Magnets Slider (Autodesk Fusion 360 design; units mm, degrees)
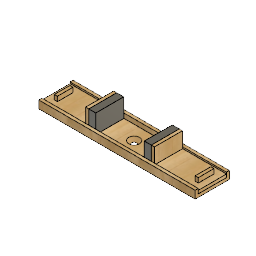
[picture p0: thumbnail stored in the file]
parameter "Mag_L" = 180
parameter "Mag_W" = 120
parameter "Mag_T" = 45
sketch "Sketch1"
  dimension "d1" = 220 (= "Mag_L + 40 mm")
  dimension "d2" = 1000
extrude "Extrude1" new body sketch "Sketch1" blind 50
sketch "Sketch2" plane through (0, 0, 50) normal (0, 0, 1) x axis (-1, 0, 0)
  dimension "d6" = 180 (= "Mag_L")
extrude "Extrude2" cut sketch "Sketch2" against normal blind 30
sketch "Sketch4" plane through (0, 0, 20) normal (0, 0, 1) x axis (-1, 0, 0)
  dimension "d10" = 70
extrude "Extrude3" cut sketch "Sketch4" against normal blind 20 taper -45
component_from_bodies "Body->Comp"
sketch "Sketch1" plane through (0, 0, 20) normal (0, 0, 1) x axis (-1, 0, 0)
  dimension "d13" = 280
  dimension "d14" = 180 (= "Mag_L")
  dimension "d22" = 0
  dimension "d23" = 0
  dimension "d24" = 0
  dimension "d25" = 0
extrude "Extrude1" new body sketch "Sketch1" along normal blind 20
sketch "Sketch2" plane through (125, 0, 0) normal (-1, 0, 0) x axis (0, -1, 0)
  dimension "d18" = 180 (= "Mag_L")
  dimension "d19" = 120 (= "Mag_W")
extrude "Extrude2" add sketch "Sketch2" along normal blind 20
position "Position1"
joint "Assemble1" sketch "Sketch2" alignAngle 0 alignOffsetX 0 alignOffsetY 0 alignOffsetZ 0
copy_paste_bodies "CopyPasteBodies1"
position "Position2" TranslateAlongX 350
move "Move1"
joint "Assemble2" alignAngle 180 alignOffsetX 0 alignOffsetY 0 alignOffsetZ 0
sketch "Sketch1" plane through (-238.0829, 32.402, -22.7743) normal (1, 0, 0) x axis (0, 1, 0)
  dimension "d55" = 120 (= "Mag_W")
  dimension "d56" = 180 (= "Mag_L")
extrude "Extrude1" new body sketch "Sketch1" along normal blind 45 (= "Mag_T")
sketch "Sketch2" plane through (161.9171, 0, 0) normal (-1, 0, 0) x axis (0, -1, 0)
  dimension "d61" = 120 (= "Mag_W")
  dimension "d62" = 180 (= "Mag_L")
extrude "Extrude2" new body sketch "Sketch2" along normal blind 45 (= "Mag_T")
sketch "Sketch5" plane through (0, 0, 28.5535) normal (0, 0, 1) x axis (-1, 0, 0)
  dimension "d66" = 20
  dimension "d67" = 100
extrude "Extrude3" add sketch "Sketch5" along normal blind 30
sketch "Sketch6" plane through (0, 0, 28.5535) normal (0, 0, 1) x axis (-1, 0, 0)
  dimension "d71" = 20
  dimension "d72" = 100
  dimension "d75" = 50
extrude "Extrude1" add sketch "Sketch6" along normal blind 30
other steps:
base_feature "Base Feature1" OffsetX 0 OffsetY 0 OffsetZ 0 AngleZ 0
base_feature "Base Feature1"
create_component "CreateComponent1"
remove_body "RemoveBody1"
create_component "CreateComponent1"
joint_origin "JointOrigin2" OffsetX 0 OffsetY 0 OffsetZ 0 AngleZ 0
joint_origin "JointOrigin2" OffsetX 0 OffsetY 0 OffsetZ 0 AngleZ 0
create_component "CreateComponent1"
joint_origin "JointOrigin1" OffsetX 0 OffsetY 0 OffsetZ 0 AngleZ 0
joint_origin "JointOrigin3" OffsetX 0 OffsetY 0 OffsetZ 0 AngleZ 0
create_component "CreateComponent2"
